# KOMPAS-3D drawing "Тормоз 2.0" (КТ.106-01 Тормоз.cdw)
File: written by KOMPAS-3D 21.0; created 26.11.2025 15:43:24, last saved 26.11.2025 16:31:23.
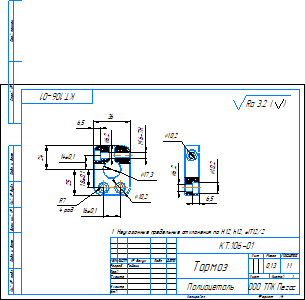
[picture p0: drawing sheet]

Sheet 1: A4, landscape

Document properties: Автор: User; Полное имя файла: C:\Users\User\Desktop\Pelorus PRO доработки\Тормоз\КТ.106-01 Тормоз.cdw; Знак неуказанной шероховатости: 4; Параметр неуказанной шероховатости: Ra 3.2; Масса: 0.133662

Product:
- Part/product: Тормоз 2.0
    Масса: 0.133662

Title block, sheet 1: Наименование: Тормоз; designation: КТ.106-01; Материал: Полиацеталь; Масса: 0,13; Количество листов документа: 1; organisation: ООО ТПК Пегас; Форматы листов документа: A4; Разработал: Гайсин

Views: Вид 1, Местный разрез 1, Снизу, Проекционный вид 2
Referenced files in C:\Users\User\Desktop\Pelorus PRO доработки\Тормоз\: КТ.106-01.m3d
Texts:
  Тормоз 2.0
  Ra 3.2
  Ra 3.2 ( )
Dimensions and other numbers on the sheet: 36; 17,3; 18±0,1; 25; 16±0,1; 24; 6,5; 14±0,1; 6-7Н; 7; 4 рад; 10,2; 6,2; 1:1; 1; 0,13

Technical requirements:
  Неуказанные предельные отклонения по H12, h12,  IT12/2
